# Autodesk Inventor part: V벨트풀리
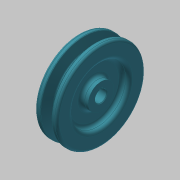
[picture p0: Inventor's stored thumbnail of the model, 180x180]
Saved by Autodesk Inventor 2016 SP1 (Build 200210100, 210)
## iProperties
Created: 2015-11
Part Number: V벨트풀리
Material: 강철, 탄소
Document SubType Name: Modeling
Designer: mduedu
Density: 1 g/cm^3
Appearance: 커뎃 파란색
Author: mduedu
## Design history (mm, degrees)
sketch "스케치1"
  geometry: L1 (-9.5, 0)-(9.5, 0); L2 (0, 0)-(0, 37.7); L3 (-4.825, 37.7)-(-9.5, 37.7); L4 (-9.5, 37.7)-(-9.5, 0); L5 (0, 28.7)-(-2.074, 28.7); L6 (-2.074, 28.7)-(-4.825, 37.7); L7 (4.825, 37.7)-(9.5, 37.7); L8 (9.5, 37.7)-(9.5, 0); L9 (0, 28.7)-(2.074, 28.7); L10 (2.074, 28.7)-(4.825, 37.7); L11 (-9.5, 35)-(9.5, 35); 3 further points
  constraints: 22 end point, 7 point on line, 4 perpendicular, 3 symmetric about line, 1 coincident, 1 horizontal, 1 horizontal alignment, 1 midpoint, 1 vertical
  dimensions: "d0" = 19 distance of L1.start L1.end; "d2" = 75.4 diameter of L2.end L1 (derived); "d3" = 34 deg angle of L10 L6; "d4" = 6.3 distance between parallel lines of L11 L9; "d5" = 2.7 distance between parallel lines of L7 L11; "d6" = 8 distance of point (4, 35) point (-4, 35); "d7" = 70 diameter of L11 L1
revolve "회전1" sketch "스케치1" stored, may be unused: angle "d8" = 90 deg
sketch "스케치2"
  geometry: C1 r 24 at (0, 0); C2 r 11 at (0, 0); 1 further point
  constraints: 2 centre point, 2 coincident
  dimensions: "d9" = 48 diameter of C1; "d10" = 22 diameter of C2
extrude "돌출1" cut sketch "스케치2" distance "d11" = 6; taper "d12" = 0 deg
fillet "모깎기1" dims "d13" = 3
fillet "모깎기2" dims "d14" = 3
fillet "모깎기3" dims "d15" = 1, "d16" = 0.5, "d17" = 2
hole "구멍1" diameter "d20" = 10; stored, may be unused: countersink angle "d24" = 90 deg, drill point angle "d26" = 118 deg; dims "d18" = 10, "d19" = 10, "d21" = 6, "d22" = 4, "d23" = 2, "d25" = 8
sketch "스케치3"
  geometry: L1 (-1.5, 0)-(1.5, 0); L2 (1.5, 0)-(1.5, 6.4); L3 (1.5, 6.4)-(-1.5, 6.4); L4 (-1.5, 6.4)-(-1.5, 0); 2 further points
  constraints: 8 end point, 2 parallel, 1 coincident, 1 horizontal, 1 midpoint, 1 perpendicular
  dimensions: "d27" = 3 distance of L2.end L3.end; "d29" = 6.4 distance of L3.end L1.start
extrude "돌출2" cut sketch "스케치3" stored distance "d30" = 6; taper "d31" = 0 deg
chamfer "모따기1" distance "d32" = 0.5; stored, may be unused: second distance "d33" = 2, angle "d34" = 45 deg
node "솔리드1"
mirror "대칭1"
